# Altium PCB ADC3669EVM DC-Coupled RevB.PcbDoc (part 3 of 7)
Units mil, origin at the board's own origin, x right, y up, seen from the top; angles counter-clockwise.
Board outline 5000 x 2716.54 mil, 12 copper layers (Top Layer, L2 GND, L3 SIG, L4 GND, L5 PWR, L6 GND, L7 GND, L8 PWR, L9 GND, L10 PWR, L11 GND, Bottom Layer), stack 61 mil thick; 546 components, 341 nets, 2088 pads, 1256 vias.
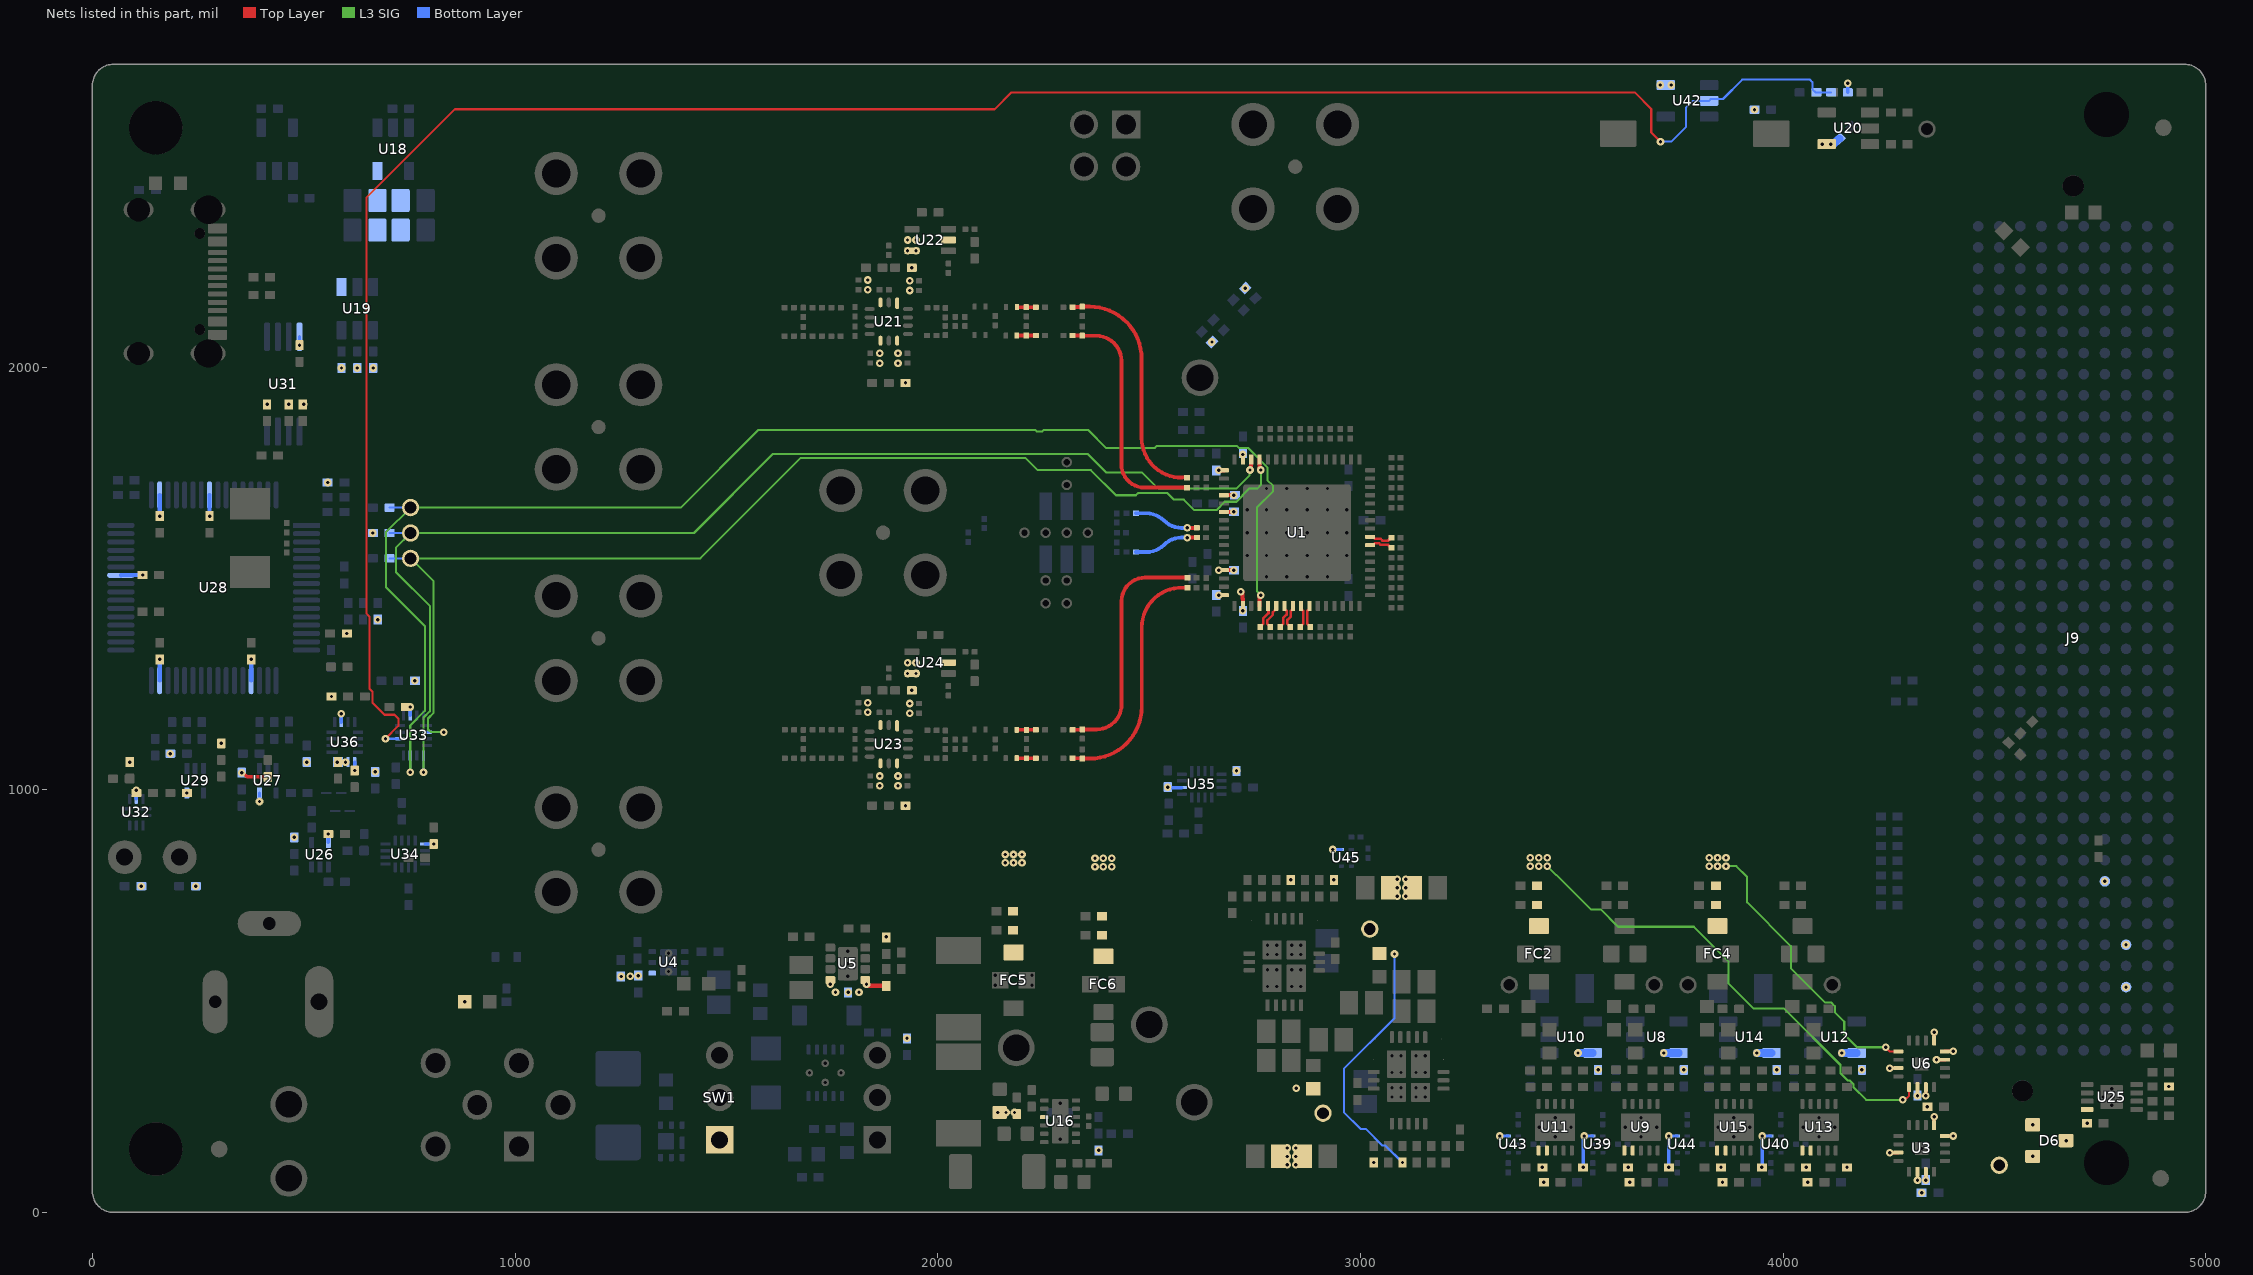
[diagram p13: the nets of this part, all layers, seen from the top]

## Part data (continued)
C96 C99 C115 C118: library part 0201RFCaps0738, "CAP THIN FILM 1PF 50V 0201", Alt Manufacturer=-, Manufacturer="KYOCERA AVX", Operating Temperature="-55°C ~ 125°C", Tolerance=±0.02pF, Voltage - Rated="50 V"
C126 C127 C130 C131 C140 C144 C145 C146 C149 C150 C159 C163: library part capcc05522, "CAP CER 10000PF 10V X7R 0201", Manufacturer="TDK Corporation", Operating Temperature="-55°C ~ 125°C", Ratings=AEC-Q200, Supplier Part Number 1=445-12059-1-ND, Temperature Coefficient=X7R, Tolerance=±10%, Voltage - Rated=10V
C128 C129 C132 C133 C147 C148 C151 C152: library part capcc04220, "CAP CER 2200PF 10V X7R 0201", Manufacturer="KYOCERA AVX", Operating Temperature="-55°C ~ 125°C", Ratings=-, Supplier Part Number 1=478-10777-1-ND, Temperature Coefficient=X7R, Tolerance=±10%, Voltage - Rated=10V
C135 C138 C154 C157: library part 0201RFCaps0065, "CAP CER 2PF 25V C0G/NP0 0201", Alt Manufacturer=-, Manufacturer="Murata Electronics", Operating Temperature="-55°C ~ 125°C", Temperature Coefficient="C0G, NP0", Tolerance=±0.05pF, Voltage - Rated=25V
C136 C155: library part 0201RFCaps0260, "CAP CER 0.7PF 25V C0G/NP0 0201", Alt Manufacturer=-, Manufacturer="Murata Electronics", Operating Temperature="-55°C ~ 125°C", Temperature Coefficient="C0G, NP0", Tolerance=±0.1pF, Voltage - Rated=25V
C137 C156: library part 0201RFCaps0405, "CAP CER 6.6PF 25V NP0 0201", Alt Manufacturer=-, Manufacturer="Murata Electronics", Operating Temperature="-55°C ~ 125°C", Temperature Coefficient="C0G, NP0", Tolerance=±0.25pF, Voltage - Rated=25V
C181 C182: library part capcc08351, "CAP CER 18PF 25V C0G/NP0 0201", Manufacturer="Murata Electronics", Operating Temperature="-55°C ~ 125°C", Ratings=-, Supplier Part Number 1=490-14486-1-ND, Temperature Coefficient="C0G, NP0", Tolerance=±2%, Voltage - Rated=25V
D1 D2 D7: library part cmp00247, "LED GREEN CLEAR CHIP SMD", Alt Manufacturer=-, Color=Green, Current Rating (Amps)=20mA, Manufacturer="Lite-On Inc.", Supplier Part Number 1=160-1888-1-ND, Voltage - Forward (Vf) (Typ)=3.2V
D3: library part cmp00440, "24.4V Clamp 24.6A Ipp Tvs Diode", Alt Manufacturer=-, Manufacturer=Littlefuse, Supplier Part Number 1=SMBJ15CALFCT-ND
D4: library part cmp00438, "DIODE SCHOTTKY 30V 1A SOD123", Alt Manufacturer="Rohm Semiconductor", Alt PartNumber=RB160M-30TR, Color=-, Manufacturer=Onsemi, Supplier Part Number 1=MBR130T1GOSCT-ND
D5: "Diode 40 V 3A Surface Mount PMDTM", Manufacturer="Rohm Semiconductor", Supplier Part Number 1=RBR3LAM40ACT-ND
D6: "Diode Array 1 Pair Common Cathode 20 V 400mA (DC)", Alt Manufacturer=-, Manufacturer="Diodes Inc", Supplier Part Number 1=SDM40E20LC-7DICT-ND
F1: library part cmp00082, "FUSE BOARD MOUNT 2.5A 32VDC 1206", Alt Manufacturer=-, Current Rating (Amps)="2.5 A", Manufacturer="Bourns Inc.", Supplier Part Number 1=SF-1206FP250-2CT-ND, Voltage Rating - DC="32 V"
F2: library part cmp00325, "EMI Filter Circuits 40 DB 50V 10A", Alt Manufacturer=-, Manufacturer="Murata Electronics", Supplier Part Number 1=81-BNX002-11
FB1 FB2 FB3 FB4 FB5 FB6 FB8: library part dcp00004, "8.5 Ohms @ 100 MHz 1 Power Line Ferrite Bead 0603 (1608 Metric) 8A 4mOhm", Current=8A, Manufacturer=Murata, Operating Temperature="-55°C ~ 125°C", Supplier Part Number 1=490-BLE18PS080SN1DCT-ND, Temperature Coefficient=-
FB11 FB12: library part dcp00209, "0402 (1005) 150OHM (TYP.) 1000MA", Current=1A, Manufacturer="Murata Electronics", Operating Temperature="-40°C ~ 85°C", Supplier Part Number 1=490-18375-1-ND, Temperature Coefficient=-
FC1 FC2 FC3 FC4 FC5 FC6: library part dcp00001, "Feed through capactior 27uF", Current=6A, Manufacturer=Murata, Operating Temperature="-40°C ~ 85°C", Supplier Part Number 1=490-6984-1-ND, Temperature Coefficient=-, Tolerance=±20%, Voltage - Rated=6.3V
FID1 FID2 FID3: library part mech00005, "Fiducial", Manufacturer=-
H5 H6: library part cmp00097, "Hex Standoff Threaded #4-40 Stainless Steel 1.250\" (31.75mm) 1 1/4", Alt Manufacturer=-, Manufacturer="RAF Electronic Hardware", Supplier Part Number 1=1772-1827-ND
J1: "Power Jack, mini, 2.1mm OD, R/A, TH", Alt Manufacturer=-, Manufacturer=Switchcraft, Supplier Part Number 1=SC1313-ND
J2 J4 J5 J6 J7 J8: "SMA Connector Jack, Female Socket 50Ohm Surface Mount, Through Hole Solder", Alt Manufacturer=-, Manufacturer="Amphenol RF", Supplier Part Number 1=ACX1962-ND
J3: "Header, 100mil, 2x2, Gold, TH", Alt Manufacturer="Sullins Connector Solutions", Alt PartNumber=PBC02DAAN, Color=-, Manufacturer=Samtec, Supplier Part Number 1=S2011E-02-ND
J9: "FMC, High Density Array, Male / EVM Connector 40x10", Alt Manufacturer=-, Manufacturer=Samtec, Supplier Part Number 1=SAM8730-ND
J10: "USB - C (Type - C) USB 2.0 Receptacle Connector 24 Position Surface Mount, Right Angle; Through Hole", Manufacturer=GCT, Supplier Part Number 1=2073-USB4105-GF-ACT-ND
L1 L2 L3 L4: library part indrf00113, "FIXED IND 2NH 600MA 120MOHM SMD", Alternate Manufacturer=-, Current Rating="600 mA", DC Resistance (DCR)="120mOhm Max", Frequency - Self Resonant=9GHz, Manufacturer="Murata Electronics", Operating Temperature="-55°C ~ 125°C", Package=0201, Q @ Freq="20 @ 500MHz", Supplier Part Number 1=490-13895-1-ND, Tolerance=±0.1nH
L5 L7 L9 L11: library part indrf00014, "RF Ceramic Chip Inductors", Alternate Manufacturer=-, Current Rating="260 mA", DC Resistance (DCR)="370 mΩ", Frequency - Self Resonant="6.25 GHz", Manufacturer=Coilcraft, Operating Temperature="-40°C ~ 125°C", Package=0201, Tolerance=±5%
L6 L8 L10 L12: library part indrf00011, "RF Ceramic Chip Inductors", Alternate Manufacturer=-, Current Rating="440 mA", DC Resistance (DCR)="155 mΩ", Frequency - Self Resonant="8 GHz", Manufacturer=Coilcraft, Operating Temperature="-40°C ~ 125°C", Package=0201, Tolerance=±5%
LBL1: library part cmp00106, "Thermal Transfer Printable Labels, 0.650\" W x 0.200\" H - 10,000 per roll", Alt Manufacturer=-, Manufacturer=Brady, Supplier Part Number 1=2267-THT-14-423-10-ND
Logo1: library part cmp00105, "FDL", Alt Manufacturer=-
Logo2: library part cmp00102, "FCC_disclaimer", Alt Manufacturer=-
Logo3: library part cmp00317, Alt Manufacturer=-, PartNumber="ESD Logo"
Logo4: library part cmp00101, Alt Manufacturer=-, PartNumber=WEEE_Minimum
LOGO5: library part cmp00103, "CE_Mark", Alt Manufacturer=-
Logo6: library part cmp00104, "Texas Instrument Corporate Signature", Alt Manufacturer=-, PartNumber="TI Bug"
NT1 NT2: library part cmp00320, "Single Point net tie", Alt Manufacturer=-, PartNumber=NetTie
PP1: "Probe Point that can be used in lue of a test point", Alt Manufacturer=-
PP2 PP3 PP4 PP5 PP6 PP8 PP11 PP12 PP13 PP14: library part cmp00025, "Probe Point that can be used in lue of a test point", Alt Manufacturer=-
Q1: library part cmp00439, "Bipolar (BJT) Transistor NPN 40 V 200 mA 300MHz 300 mW", Alt Manufacturer=-, Manufacturer=Onsemi, PartNumber=SMMBT3904LT1G, Supplier Part Number 1=SMMBT3904LT1GOSCT-ND
Q2: library part cmp00159, "MOSFET, N-CH, 20 V, 10 A", Alt Manufacturer=-, Manufacturer="Texas Instruments", Supplier Part Number 1=296-39992-1-ND
R1 R188 R259 R266: library part RSMD040200005, "RES SMD 1K OHM 0.5% 1/16W 0402", Manufacturer="Panasonic Electronic Components", Operating Temperature="-55°C ~ 155°C", Power (Watts)="0.063W, 1/16W", Ratings=AEC-Q200, Resistance="1 kΩ", Supplier Part Number 1=P1.0KDECT-ND, Temperature Coefficient=±25ppm/°C, Tolerance=±0.5%
R2: library part RSMD040200026, "RES SMD 1M OHM 1% 1/10W 0402", Manufacturer="Panasonic Electronic Components", Operating Temperature="-55°C ~ 155°C", Power (Watts)="0.1W, 1/10W", Ratings=AEC-Q200, Resistance="1 MΩ", Supplier Part Number 1=P1.00MLCT-ND, Temperature Coefficient=±100ppm/°C, Tolerance=±1%
R3 R185 R186 R187 R207 R210 R245 R246 R249 R250 R251 R252 R253 R254 R257 R260 R261: library part RSMD040202592, "RES 4.7K OHM 1% 1/10W 0402", Manufacturer="Panasonic Electronic Components", Operating Temperature="-55°C ~ 175°C", Power (Watts)="0.1W, 1/10W", Ratings=AEC-Q200, Resistance="4.7 kΩ", Supplier Part Number 1=10-ERJ-H2RF4701XCT-ND, Temperature Coefficient=±100ppm/°C, Tolerance=±1%
R4: library part RSMD040201732, "RES SMD 26.7KOHM 0.1% 1/16W 0402", Manufacturer="Panasonic Electronic Components", Operating Temperature="-55°C ~ 155°C", Power (Watts)="0.063W, 1/16W", Ratings=AEC-Q200, Resistance="26.7 kΩ", Supplier Part Number 1=P17789CT-ND, Temperature Coefficient=±15ppm/°C, Tolerance=±0.1%
R5: library part RSMD040200944, "RES SMD 162K OHM 1% 1/10W 0402", Manufacturer="Panasonic Electronic Components", Operating Temperature="-55°C ~ 155°C", Power (Watts)="0.1W, 1/10W", Ratings=AEC-Q200, Resistance="162 kΩ", Supplier Part Number 1=P162KLCT-ND, Temperature Coefficient=±100ppm/°C, Tolerance=±1%
R6 R7 R8 R13 R14 R19 R22 R28 R31 R36 R39 R45 R48 R61 R62 R64 R65 R73 R78 R125 R153 R172 R196 R209 R216 R241 R242 R243: library part RSMD040200314, "RES SMD 10K OHM 1% 1/10W 0402", Manufacturer="Panasonic Electronic Components", Operating Temperature="-55°C ~ 155°C", Power (Watts)="0.1W, 1/10W", Ratings=AEC-Q200, Resistance="10 kΩ", Supplier Part Number 1=P10.0KLCT-ND, Temperature Coefficient=±100ppm/°C, Tolerance=±1%
R9: library part RSMD040202967, "RES SMD 5.6K OHM 0.1% 1/16W 0402", Manufacturer="Panasonic Electronic Components", Operating Temperature="-55°C ~ 155°C", Power (Watts)="0.063W, 1/16W", Ratings=AEC-Q200, Resistance="5.6 kΩ", Supplier Part Number 1=P5.6KCNCT-ND, Temperature Coefficient=±15ppm/°C, Tolerance=±0.1%
R10: library part RSMD040202418, "RES SMD 37.4KOHM 0.1% 1/16W 0402", Manufacturer="Panasonic Electronic Components", Operating Temperature="-55°C ~ 155°C", Power (Watts)="0.063W, 1/16W", Ratings=AEC-Q200, Resistance="37.4 kΩ", Supplier Part Number 1=P37.4KDCCT-ND, Temperature Coefficient=±25ppm/°C, Tolerance=±0.1%
R11 R12 R44 R52 R240: library part RSMD040200520, "RES SMD 12K OHM 0.1% 1/16W 0402", Manufacturer="Panasonic Electronic Components", Operating Temperature="-55°C ~ 155°C", Power (Watts)="0.063W, 1/16W", Ratings=AEC-Q200, Resistance="12 kΩ", Supplier Part Number 1=P12KCPCT-ND, Temperature Coefficient=±10ppm/°C, Tolerance=±0.1%
R15 R67: library part RSMD040203749, "RES SMD 80.6KOHM 0.1% 1/16W 0402", Manufacturer="Panasonic Electronic Components", Operating Temperature="-55°C ~ 155°C", Power (Watts)="0.063W, 1/16W", Ratings=AEC-Q200, Resistance="80.6 kΩ", Supplier Part Number 1=P80.6KDCCT-ND, Temperature Coefficient=±25ppm/°C, Tolerance=±0.1%
R16: library part RSMD040203923, "RES SMD 9.31KOHM 0.1% 1/16W 0402", Manufacturer="Panasonic Electronic Components", Operating Temperature="-55°C ~ 155°C", Power (Watts)="0.063W, 1/16W", Ratings=AEC-Q200, Resistance="9.31 kΩ", Supplier Part Number 1=P9.31KDCCT-ND, Temperature Coefficient=±25ppm/°C, Tolerance=±0.1%
R17 R26 R34 R43 R51 R69 R74 R75 R79 R80 R111 R121 R124 R126 R127 R128 R139 R178 R179 R180 R181 R189 R190 R191 R193 R194 R195 R197 R198 R199 R200 R201 R204 R212 R213 R214 R215 R218 R219 R220 R222 R248 R256 R262 R263 R267: library part RSMD040200001, "RES SMD 0 OHM JUMPER 1/10W 0402", Manufacturer="Panasonic Electronic Components", Operating Temperature="-55°C ~ 155°C", Power (Watts)="0.1W, 1/10W", Ratings=AEC-Q200, Resistance="0 Ω", Supplier Part Number 1=P0.0JCT-ND, Temperature Coefficient=-, Tolerance=Jumper
R18: library part RSMD040202615, "RES SMD 4.87KOHM 0.1% 1/16W 0402", Manufacturer="Panasonic Electronic Components", Operating Temperature="-55°C ~ 155°C", Power (Watts)="0.063W, 1/16W", Ratings=AEC-Q200, Resistance="4.87 kΩ", Supplier Part Number 1=P4.87KDCCT-ND, Temperature Coefficient=±25ppm/°C, Tolerance=±0.1%
R20 R29 R37 R46: library part RSMD060312209, "RES 0.02 OHM 1% 1/3W 0603", Manufacturer="Panasonic Electronic Components", Operating Temperature="-55°C ~ 155°C", Power (Watts)="0.333W, 1/3W", Ratings=AEC-Q200, Resistance="20 mΩ", Supplier Part Number 1=P17461CT-ND, Temperature Coefficient=±250ppm/°C, Tolerance=±1%
R21 R30: library part RSMD040203023, "RES SMD 51.1K OHM 1% 1/10W 0402", Manufacturer="Panasonic Electronic Components", Operating Temperature="-55°C ~ 155°C", Power (Watts)="0.1W, 1/10W", Ratings=AEC-Q200, Resistance="51.1 kΩ", Supplier Part Number 1=P51.1KLCT-ND, Temperature Coefficient=±100ppm/°C, Tolerance=±1%
R23 R32 R40 R49 R60 R63 R71 R72 R76 R77 R81 R82 R83 R84 R85 R86 R87 R88 R89 R90 R91 R92 R93 R94 R95 R96 R97 R98 R99 R100 R101 R102 R103 R104 R105 R106 R107 R108 R109 R110 R114 R115 R116 R117 R118 R119 R120 R140 R146 R147 R159 R165 R166 R272: library part RSMD020101699, "RES SMD 0 OHM JUMPER 1/20W 0201", Manufacturer="Panasonic Electronic Components", Operating Temperature="-55°C ~ 125°C", Power (Watts)="0.05W, 1/20W", Resistance="0 Ω", Supplier Part Number 1=P15979CT-ND, Tolerance=Jumper
R24 R33 R41 R50: library part RSMD040200547, "RES SMD 12.4K OHM 1% 1/10W 0402", Manufacturer="Panasonic Electronic Components", Operating Temperature="-55°C ~ 155°C", Power (Watts)="0.1W, 1/10W", Ratings=AEC-Q200, Resistance="12.4 kΩ", Supplier Part Number 1=P12.4KLCT-ND, Temperature Coefficient=±100ppm/°C, Tolerance=±1%
R25 R42: library part RSMD120607125, "RES SMD 0 OHM JUMPER 1/4W 1206", Manufacturer="Panasonic Electronic Components", Operating Temperature="-55°C ~ 155°C", Power (Watts)="0.25W, 1/4W", Ratings=AEC-Q200, Resistance="0 Ω", Supplier Part Number 1=ERJ-S080R00V-ND, Temperature Coefficient=-, Tolerance=Jumper
R27 R35: library part RSMD040203700, "RES SMD 8.06KOHM 0.1% 1/16W 0402", Manufacturer="Panasonic Electronic Components", Operating Temperature="-55°C ~ 155°C", Power (Watts)="0.063W, 1/16W", Ratings=AEC-Q200, Resistance="8.06 kΩ", Supplier Part Number 1=P17902CT-ND, Temperature Coefficient=±15ppm/°C, Tolerance=±0.1%
R38 R47: library part RSMD040203879, "RES SMD 88.7K OHM 1% 1/10W 0402", Manufacturer="Panasonic Electronic Components", Operating Temperature="-55°C ~ 155°C", Power (Watts)="0.1W, 1/10W", Ratings=AEC-Q200, Resistance="88.7 kΩ", Supplier Part Number 1=P88.7KLCT-ND, Temperature Coefficient=±100ppm/°C, Tolerance=±1%
R53: library part RSMD040201564, "RES SMD 23.2KOHM 0.1% 1/16W 0402", Manufacturer="Panasonic Electronic Components", Operating Temperature="-55°C ~ 155°C", Power (Watts)="0.063W, 1/16W", Ratings=AEC-Q200, Resistance="23.2 kΩ", Supplier Part Number 1=P23.2KDCCT-ND, Temperature Coefficient=±25ppm/°C, Tolerance=±0.1%
R54 R58: library part CMP-0016044-3, "RES, 0, 5%, 0.75 W, AEC-Q200 Grade 0, 2010", Manufacturer=Vishay-Dale, Power_W=750mW, Supplier Part Number 1=541-0.0WCT-ND, TempCo=ppm/C, Tolerance_%=5%, Value2=0.75W, Value_Code=0000, ValueDisplayed=0
R55: library part RSMD040202194, "RES SMD 324 OHM 0.1% 1/16W 0402", Manufacturer="Panasonic Electronic Components", Operating Temperature="-55°C ~ 155°C", Power (Watts)="0.063W, 1/16W", Ratings=AEC-Q200, Resistance="324 Ω", Supplier Part Number 1=P324DCCT-ND, Temperature Coefficient=±25ppm/°C, Tolerance=±0.1%
R56 R57: library part RSMD040200357, "RES SMD 100K OHM 0.1% 1/16W 0402", Manufacturer="Panasonic Electronic Components", Operating Temperature="-55°C ~ 155°C", Power (Watts)="0.063W, 1/16W", Ratings=AEC-Q200, Resistance="100 kΩ", Supplier Part Number 1=P100KDCCT-ND, Temperature Coefficient=±25ppm/°C, Tolerance=±0.1%
R59: library part RSMD080510615, "RES SMD 0 OHM JUMPER 1/8W 0805", Manufacturer="Panasonic Electronic Components", Operating Temperature="-55°C ~ 155°C", Power (Watts)="0.125W, 1/8W", Ratings=AEC-Q200, Resistance="0 Ω", Supplier Part Number 1=P0.0ACT-ND, Temperature Coefficient=-, Tolerance=Jumper
R66: library part RSMD040200004, "RES 0 OHM JUMPER 0402 SMD", Manufacturer="Panasonic Electronic Components", Operating Temperature="-55°C ~ 155°C", Power (Watts)="0.1W, 1/10W", Ratings=AEC-Q200, Resistance="0 Ω", Supplier Part Number 1=10-ERJ-U020R00XCT-ND, Temperature Coefficient="-100/ +600ppm/°C", Tolerance=Jumper
R68: library part RSMD040203577, "RES SMD 7.87KOHM 0.1% 1/16W 0402", Manufacturer="Panasonic Electronic Components", Operating Temperature="-55°C ~ 155°C", Power (Watts)="0.063W, 1/16W", Ratings=AEC-Q200, Resistance="7.87 kΩ", Supplier Part Number 1=P7.87KDCCT-ND, Temperature Coefficient=±25ppm/°C, Tolerance=±0.1%
R70: library part RSMD040200273, "RES SMD 1.8K OHM 0.1% 1/16W 0402", Manufacturer="Panasonic Electronic Components", Operating Temperature="-55°C ~ 155°C", Power (Watts)="0.063W, 1/16W", Ratings=AEC-Q200, Resistance="1.8 kΩ", Supplier Part Number 1=10-ERA-2ARB182XCT-ND, Temperature Coefficient=±10ppm/°C, Tolerance=±0.1%
R112 R113 R122 R123 R157 R176: library part RSMD040200311, "RES SMD 10K OHM 1% 1/5W 0402", Manufacturer="Panasonic Electronic Components", Operating Temperature="-55°C ~ 155°C", Power (Watts)="0.2W, 1/5W", Ratings=AEC-Q200, Resistance="10 kΩ", Supplier Part Number 1=P17230CT-ND, Temperature Coefficient=±100ppm/°C, Tolerance=±1%
R129 R130 R134 R137 R138: library part RSMD020100423, "RES 49.9 OHM 1% 1/20W 0201 SMD", Manufacturer="Panasonic Electronic Components", Operating Temperature="-55°C ~ 125°C", Power (Watts)="0.05W, 1/20W", Resistance="49.9 Ω", Supplier Part Number 1=10-ERJ-U01F49R9CTR-ND, Temperature Coefficient=±200ppm/°C, Tolerance=±1%
R131 R136: library part RSMD020100201, "RES SMD 499 OHM 1% 1/20W 0201", Manufacturer="Panasonic Electronic Components", Operating Temperature="-55°C ~ 125°C", Power (Watts)="0.05W, 1/20W", Resistance="499 Ω", Supplier Part Number 1=P123045CT-ND, Temperature Coefficient=±200ppm/°C, Tolerance=±1%
R132 R135: library part RSMD020100013, "RES SMD 33 OHM 1% 1/20W 0201", Manufacturer="Panasonic Electronic Components", Operating Temperature="-55°C ~ 125°C", Power (Watts)="0.05W, 1/20W", Resistance="33 Ω", Supplier Part Number 1=P122944CT-ND, Temperature Coefficient=±200ppm/°C, Tolerance=±1%
R133: library part RSMD020100289, "RES SMD 100 OHM 1% 1/20W 0201", Manufacturer="Panasonic Electronic Components", Operating Temperature="-55°C ~ 125°C", Power (Watts)="0.05W, 1/20W", Resistance="100 Ω", Supplier Part Number 1=P122654CT-ND, Temperature Coefficient=±200ppm/°C, Tolerance=±1%
R141 R158 R160 R177: library part RSMD020100324, "RES 22.6 OHM 1% 1/20W 0201 SMD", Manufacturer="Panasonic Electronic Components", Operating Temperature="-55°C ~ 125°C", Power (Watts)="0.05W, 1/20W", Resistance="22.6 Ω", Supplier Part Number 1=10-ERJ-U01F22R6CTR-ND, Temperature Coefficient=±200ppm/°C, Tolerance=±1%
R142 R149 R161 R168: library part RSMD020100228, "RES SMD 127 OHM 1% 1/20W 0201", Manufacturer="Panasonic Electronic Components", Operating Temperature="-55°C ~ 125°C", Power (Watts)="0.05W, 1/20W", Resistance="127 Ω", Supplier Part Number 1=P122704CT-ND, Temperature Coefficient=±200ppm/°C, Tolerance=±1%
R143 R150 R162 R169: library part RSMD020100033, "RES SMD 40.2 OHM 1% 1/20W 0201", Manufacturer="Panasonic Electronic Components", Operating Temperature="-55°C ~ 125°C", Power (Watts)="0.05W, 1/20W", Resistance="40.2 Ω", Supplier Part Number 1=P122995CT-ND, Temperature Coefficient=±200ppm/°C, Tolerance=±1%
R144 R163: library part RSMD020100044, "RES SMD 357 OHM 1% 1/20W 0201", Manufacturer="Panasonic Electronic Components", Operating Temperature="-55°C ~ 125°C", Power (Watts)="0.05W, 1/20W", Resistance="357 Ω", Supplier Part Number 1=P122956CT-ND, Temperature Coefficient=±200ppm/°C, Tolerance=±1%
R145 R156 R164 R175: library part RSMD020100735, "RES 10K OHM 1% 1/20W 0201 SMD", Manufacturer="Panasonic Electronic Components", Operating Temperature="-55°C ~ 125°C", Power (Watts)="0.05W, 1/20W", Resistance="10 kΩ", Supplier Part Number 1=10-ERJ-U01F1002CCT-ND, Temperature Coefficient=±200ppm/°C, Tolerance=±1%
R148 R167: library part RSMD020100281, "RES SMD 66.5 OHM 1% 1/20W 0201", Manufacturer="Panasonic Electronic Components", Operating Temperature="-55°C ~ 125°C", Power (Watts)="0.05W, 1/20W", Resistance="66.5 Ω", Supplier Part Number 1=P123123CT-ND, Temperature Coefficient=±200ppm/°C, Tolerance=±1%
R151 R170: library part RSMD040200008, "RES SMD 1K OHM 5% 1/10W 0402", Manufacturer="Panasonic Electronic Components", Operating Temperature="-55°C ~ 155°C", Power (Watts)="0.1W, 1/10W", Ratings=AEC-Q200, Resistance="1 kΩ", Supplier Part Number 1=P1.0KJCT-ND, Temperature Coefficient=±200ppm/°C, Tolerance=±5%
R152 R171: library part RSMD040203233, "RES SMD 590 OHM 1% 1/10W 0402", Manufacturer="Panasonic Electronic Components", Operating Temperature="-55°C ~ 155°C", Power (Watts)="0.1W, 1/10W", Ratings=AEC-Q200, Resistance="590 Ω", Supplier Part Number 1=P590LCT-ND, Temperature Coefficient=±100ppm/°C, Tolerance=±1%
R154 R155 R173 R174: library part RSMD020100261, "RES 1.5K OHM 1% 1/20W 0201 SMD", Manufacturer="Panasonic Electronic Components", Operating Temperature="-55°C ~ 125°C", Power (Watts)="0.05W, 1/20W", Resistance="1.5 kΩ", Supplier Part Number 1=10-ERJ-U01F1501CCT-ND, Temperature Coefficient=±200ppm/°C, Tolerance=±1%
R182 R183: library part RSMD060312289, "RES SMD 0 OHM JUMPER 1/10W 0603", Manufacturer="Panasonic Electronic Components", Operating Temperature="-55°C ~ 155°C", Power (Watts)="0.1W, 1/10W", Ratings=AEC-Q200, Resistance="0 Ω", Supplier Part Number 1=P0.0GCT-ND, Temperature Coefficient=-, Tolerance=Jumper
R184 R247 R255 R258 R264: library part RSMD040202585, "RES SMD 4.7K OHM 5% 1/10W 0402", Manufacturer="Panasonic Electronic Components", Operating Temperature="-55°C ~ 155°C", Power (Watts)="0.1W, 1/10W", Ratings=AEC-Q200, Resistance="4.7 kΩ", Supplier Part Number 1=P4.7KJCT-ND, Temperature Coefficient=±200ppm/°C, Tolerance=±5%
R192: library part RSMD060309678, "RES 100 OHM 5% 1/8W 0603", Manufacturer="Panasonic Electronic Components", Operating Temperature="-55°C ~ 175°C", Package / Case=0603, Power (Watts)="0.125W, 1/8W", Ratings=AEC-Q200, Temperature Coefficient=±200ppm/°C, Tolerance=±5%
R208 R211 R221: library part RSMD040200378, "RES 100 OHM 1% 1/10W 0402", Manufacturer="Panasonic Electronic Components", Operating Temperature="-55°C ~ 175°C", Power (Watts)="0.1W, 1/10W", Ratings=AEC-Q200, Resistance="100 Ω", Supplier Part Number 1=10-ERJ-H2RF1000XCT-ND, Temperature Coefficient=±100ppm/°C, Tolerance=±1%
R217 R244: library part RSMD040201203, "RES SMD 2.2K OHM 1% 1/10W 0402", Manufacturer="Panasonic Electronic Components", Operating Temperature="-55°C ~ 155°C", Power (Watts)="0.1W, 1/10W", Ratings=AEC-Q200, Resistance="2.2 kΩ", Supplier Part Number 1=P2.20KLCT-ND, Temperature Coefficient=±100ppm/°C, Tolerance=±1%
R224 R227 R229: library part RSMD040200331, "RES SMD 10 OHM 1% 1/10W 0402", Manufacturer="Panasonic Electronic Components", Operating Temperature="-55°C ~ 155°C", Power (Watts)="0.1W, 1/10W", Ratings=AEC-Q200, Resistance="10 Ω", Supplier Part Number 1=P10.0LCT-ND, Temperature Coefficient=±100ppm/°C, Tolerance=±1%
R225: library part RSMD040200006, "RES SMD 1K OHM 1% 1/10W 0402", Manufacturer="Panasonic Electronic Components", Operating Temperature="-55°C ~ 155°C", Power (Watts)="0.1W, 1/10W", Ratings=AEC-Q200, Resistance="1 kΩ", Supplier Part Number 1=P1.00KLCT-ND, Temperature Coefficient=±100ppm/°C, Tolerance=±1%
R273 R274 R275: library part RSMD040201162, "RES SMD 2K OHM 0.1% 1/16W 0402", Manufacturer="Panasonic Electronic Components", Operating Temperature="-55°C ~ 155°C", Power (Watts)="0.063W, 1/16W", Ratings=AEC-Q200, Resistance="2 kΩ", Supplier Part Number 1=P2.0KDCCT-ND, Temperature Coefficient=±25ppm/°C, Tolerance=±0.1%
SW1: "Switch Slide SPDT 12V, 500mA", Alt Manufacturer=-, Manufacturer="Wurth Elektronik", PartNumber=450301014042, Supplier Part Number 1=710-450301014042
SW2: library part cmp00234, "SWITCH TACTILE SPST-NO 0.05A 24V", Alt Manufacturer=-, Manufacturer="TE Connectivity", Supplier Part Number 1=A101402CT-ND
SW3: library part cmp00353, "Switch Slide SPDT 12V, 500mA", Alt Manufacturer=-, Manufacturer="Wurth Elektronik", Supplier Part Number 1=710-450301014042
T2: "1:2 CORE & WIRE Transformer, 10 to 3000 MHz, 50Ω", Alt Manufacturer=-, Manufacturer=Mini-Circuits, Supplier Part Number 1=3157-TCM2-33WX+CT-ND
TP1: library part cmp00040, "Test Point, Multipurpose, Red, TH", Alt Manufacturer=-, Color=Red, Manufacturer=Keystone, Supplier Part Number 1=36-5010-ND
TP2: "Test Point, Multipurpose, Black, TH", Alt Manufacturer=-, Color=Black, Manufacturer=Keystone, PartNumber=5011, Supplier Part Number 1=36-5011-ND
TP3: library part cmp00047, "Test Point, Multipurpose, Brown, TH", Alt Manufacturer=-, Color=Brown, Manufacturer=Keystone, Supplier Part Number 1=36-5125-ND
TP4: "Test Point, Multipurpose, Orange, TH", Alt Manufacturer=-, Color=Orange, Manufacturer=Keystone, PartNumber=5013, Supplier Part Number 1=36-5013-ND
TP5 TP6: "Test Point, Miniature, Blue, TH", Alt Manufacturer=-, Color=Blue, Manufacturer=Keystone, PartNumber=5117, Supplier Part Number 1=36-5117-ND
TP8: library part cmp00045, "Test Point, Multipurpose, Blue, TH", Alt Manufacturer=-, Color=Blue, Manufacturer=Keystone, Supplier Part Number 1=36-5127-ND
TP9: library part cmp00042, "Test Point, Multipurpose, White, TH", Alt Manufacturer=-, Color=White, Manufacturer=Keystone, Supplier Part Number 1=36-5012-ND
U1: library part cmp00321, "16-Bit 500-MSPS Analog-to-Digital Converter", Alt Manufacturer=-, Manufacturer="Texas Instruments", PartNumber=ADC3669
U2: library part cmp00157, "12V, 5A, 30mΩ eFuse with Adjustable +/-15% Accurate Current Limit, DRC0010J (VSON-10)", Alt Manufacturer=-, Manufacturer="Texas Instruments"
U3 U6: "16-Bit, 4-Channel, 1-kSPS, Delta-Sigma ADC with I2C Interface, RTE0016D (WQFN-16)", Alternate Manufacturer="Texas Instruments", Alternate PartNumber=ADS1119IRTET, Operating Temperature Range="-40 to 125 C"
U4: library part cmp00251, "300-mA, 18-V, Ultra-Low IQ, Low-Dropout Linear Voltage Regulator With Power-Good", Alt Manufacturer=-, Manufacturer="Texas Instruments", PartNumber=TPS7A2501DRV
U5: "17V Input 2A Synchronous Step-Down Converter MicroSiP Module With Integrated Inductor, SIL0008D (uSIP-8)", Alternate Manufacturer="Texas Instruments", Alternate PartNumber=TPS82140SILT
U7 U17: "3-V to 17-V, 3-A Low-Noise and Low-Ripple Buck Power Module with Integrated Ferrite Bead Filter Compensation", Alt Manufacturer=-, Manufacturer="Texas Instruments", Max Supply Voltage=17V, Min Supply Voltage=3V, Nominal Supply Current=5mA, Operating Temperature Range="-55°C to +125°C", Output Voltage=0.8-5.5V, PartNumber=TPSM82913RDU, Switching Frequency=1/2.2MHz
U8 U10 U12 U14: "26V, 350kHz current sense amplifier", Alt Manufacturer="Texas Instruments", Alt PartNumber=INA180B1IDBVT
U9 U11 U13 U15: library part cmp00169, "1-A, ultra-low noise, ultra-high PSRR, RF voltage regulator", Alt Manufacturer=-, Manufacturer="Texas Instruments", Supplier Part Number 1=296-TPS7A9401DSCRCT-ND
U16: "Low-Noise Positive- and Negative-Output Charge Pump With Integrated LDO", Alt Manufacturer=-, Manufacturer="Texas Instruments"
U18: "150-mA, 30-V, ultra-low-IQ, low-dropout voltage regulator with reverse current protection and enable", Alt Manufacturer=-, Manufacturer="Texas Instruments", Supplier Part Number 1=296-35484-1-ND
U19: "3 Rail Simple Power Sequencer with Fixed Time Delay", Manufacturer="Texas Instruments"
U20: library part cmp00229, "Push-pull, supply voltage supervisor with manual reset", Alt Manufacturer="Texas Instruments", Alt PartNumber=TPS3125J18DBVT, Color=-
U21 U23: "8GHz Ultra Wideband Fully Differential Amplifier, RMS0014A (UQFN-14)", Alternate Manufacturer="Texas Instruments", Alternate PartNumber=LMH5401IRMST, Operating Temperature Range="-40 to 85 C", Rating=Catalog
U22 U24: Alt Manufacturer="Texas Instruments", Supplier Part Number 1=296-35916-1-ND
U25: library part cmp00154, "EEPROM 64K 8KX8 1.8V SER EE IND 1/4AWP RPO", Alt Manufacturer=-, Manufacturer=Microchip, Supplier Part Number 1=24LC64FT-I/MNYCT-ND
U26: "0.8V→3.6V Single Bus Buffer Gate With 3-State Outputs. Active high enable.", Alt Manufacturer=-, Manufacturer="Texas Instruments"
U27: "Single Bus Buffer Gate With 3-State Outputs. Active high enable.", Alt Manufacturer=-, Manufacturer="Texas Instruments"
U28: library part cmp00204, "USB Interface IC USB HS to Quad UART/ SPI/JTAG/I2C LQFP-6", Alt Manufacturer=FTDI, Alt PartNumber=FT4232HL-TRAY, Color=-, Supplier Part Number 1=768-1026-1-ND
U29: "Single Bus Buffer Gate With 3-State Outputs. Active low enable.", Alt Manufacturer=-, Manufacturer="Texas Instruments"
U31: library part cmp00156, "1K Microwire Compatible Serial EEPROM", Alt Manufacturer=-, Manufacturer="Microchip Technology", Supplier Part Number 1=93LC46B-I/ST-ND
U32: library part cmp00300, "ESD-Protected, Low Capacitance, 2-Channel, 2:1 Switch, With Powered-off Protection", Alt Manufacturer=-, Manufacturer="Texas Instruments", PartNumber=TMUX154ERSWR
U33: "Low-Voltage 4-Bit 1-of-2 FET Multiplexer/Demultiplexe", Color=-, Manufacturer="Texas Instruments", PartNumber=SN74CBTLV3257RSVR, Supplier Part Number 1=296-35586-1-ND
U34 U35 U36: library part cmp00171, "Translation - Voltage Levels 4-bit dual-supply bus transceiver with 3-state outputs and independent direction control inputs", Alt Manufacturer="Texas Instruments", Alt PartNumber=SN74AXC4T774RSV, Color=-, Supplier Part Number 1=296-24741-1-ND
U39 U40 U43 U44 U45: library part cmp00518, "Low-Power Single 2-Input Positive-AND Gate", Color=-, Manufacturer="Texas Instruments", PartNumber=SN74AUP1G08DRYR, Supplier Part Number 1=296-SN74AUP1G08DRYRCT-ND
U41: "380-nA voltage monitor for 12-V rails", Alt Manufacturer="Texas Instruments", Alt PartNumber=TPS3847108DBVT
U42: "Single 1.65-V to 5.5-V inverter", Alt Manufacturer=-, Manufacturer="Texas Instruments"
Y1: library part cmp00323, "Crystal, 12 MHz, 18 pF, SMD", Frequency Stability=+/-30ppm, Frequency_Fixed=12MHz, Manufacturer="Abracon Corporation", Supplier Part Number 1=535-10634-1-ND
ZZ1: library part CMP-0003616-3, "This Assembly Note is for PCB labels only"
ZZ2: library part CMP-0077236-1
ZZ3: library part CMP-0077237-1
ZZ4: library part CMP-0077238-1

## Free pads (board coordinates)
  round 0 hole 105.91 unplated mask+1.97: 21(4765.34,117.76) 21(4765.42,2597.78)

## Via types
v1: diameter 18, hole 8, Top Layer to Bottom Layer, tented both sides, 1256 vias

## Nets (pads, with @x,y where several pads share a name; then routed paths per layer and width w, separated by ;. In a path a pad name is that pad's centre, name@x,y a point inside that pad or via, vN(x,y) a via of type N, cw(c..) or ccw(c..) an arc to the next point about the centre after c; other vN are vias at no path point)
1p8V_Utility: C9.2 C90.2 C165.2 C173.2 C186.1 C187.1 C190.1 R9.2 R79.2 R112.1 R113.1 R125.2 R178.2 R188.1 R189.2 R249.2 R250.2 R257.2 U4.1 U20.5 U26.5 U27.5 U34.13 U35.14 U36.13 U42.5 | length 226.9
  Top Layer w8: v1(353.29,1040.48) 356,1040.48 365.84,1030.63 C173.2@415.07,1030.63
  Bottom Layer w8: v1(395.38,972.36) U27.5@395.38,992.36 ; U26.5@558.2,875.37 v1(558.2,895.37) ; v1(620.5,1045.51) U36.13@620.5,1065.51 ; U34.13@787.43,871.69 v1(807.43,871.69) ; v1(2544.26,1006.25) 2545.25,1005.26 U35.14@2577.41,1005.26 ; v1(4152.97,2672) 4153.04,2671.93 4153.04,2650.07 R250.2@4153.11,2650
  Bottom Layer w18: v1(4113.11,2527.6) 4119.83,2527.6 4132.24,2540 C90.2@4133.43,2540
  other v1: 1251.56,558.31 1272.56,558.98 1291.77,560.08 477.93,887.44 669.05,1042.41 2706.9,1044.63 304.91,1109.85 663.63,1607.55 2648.77,2059.39 2727.34,2186.89 4093.11,2527.6 3932.48,2609.21 3709.64,2667.4 3735.67,2667.4
2p3V_LDO: C19.2 C20.2 C23.2 C30.2 C37.2 C44.2 FB2.2 PP2.1 R16.2 R22.2 R31.2 R39.2 R48.2 U9.1 U9.2 U11.1 U11.2 U13.1 U13.2 U15.1 U15.2 | length 612
  Bottom Layer w5: v1(3080.72,611.39) 3080.72,459.59 2960.99,339.86 2960.99,236.79 3000.1,197.68 3012.94,197.68 3052.06,158.56 3059.14,158.56 v1(3099.64,118.06)
  other v1: 3434.07,71.52 3637,71.52 3856.75,71.52 4058.31,71.52 3430.56,106.52 3633.49,106.52 3853.24,106.52 4054.8,106.52 3086.97,748.48 3106.97,748.48 3086.97,768.48 3106.97,768.48 3086.97,788.48 3106.97,788.48
3p3V_AUX: D6.1 J9.D32
  other v1: 4590.63,207.4 4761.42,783.27
3p3V_EEPROM: C164.2 D6.3 R184.2 U25.8
  other v1: 4670,170 4719.22,211.18 4912.84,297.98
3p3V_Utility: C5.2 C6.2 C10.2 C11.2 C12.2 C22.2 C29.2 C36.2 C43.2 C168.2 C169.2 C170.2 C171.2 C172.2 C176.2 C180.2 C183.2 C184.2 C189.2 D2.1 D6.2 FB11.1 FB12.1 R6.2 R10.2 R13.2 R19.2 R28.2 R36.2 R45.2 R64.2 R209.2 R217.2 R224.2 R241.2 R242.2 R243.2 R245.2 R246.2 R247.2 R254.2 R255.2 R264.2 R273.2 R274.2 R275.2 U3.1 U3.7 U3.10 U3.11 U3.16 U5.4 U5.5 U6.1 U6.7 U6.10 U6.11 U6.15 U6.16 U8.5 U10.5 U12.5 U14.5 U28.20 U28.31 U28.42 U28.50 U28.56 U29.5 U31.8 U32.9 U33.14 U36.6 U36.14 U36.15 U36.16 U39.6 U40.6 U43.6 U44.6 U45.6 | length 1066.9
  Top Layer w8: v1(4252.68,141.6) U3.7@4272.68,141.6 ; v1(4252.69,341.6) U6.7@4272.68,341.6 ; v1(4317.96,76.33) U3.10@4317.96,96.33 ; v1(4317.96,276.32) U6.10@4317.96,296.33 ; v1(4337.64,76.33) U3.11@4337.64,96.33 ; v1(4337.65,276.32) U6.11@4337.64,296.33 ; U3.1@4357.33,206.56 v1(4357.33,226.56) ; U6.1@4357.33,406.56 v1(4357.33,426.56) ; v1(4362.92,361.28) U6.15@4382.92,361.29 ; U3.16@4382.92,180.97 v1(4402.92,180.97) ; U6.16@4382.92,380.97 v1(4402.92,380.97)
  Top Layer w10: v1(1831.47,540.26) ccw(c1835.57,540.26) 1835.57,536.15 R10.2@1878.52,536.15
  Bottom Layer w8: U32.9@104,978.5 v1(104,998.5) ; v1(490.07,2051.88) U31.8@490.07,2071.88 ; U36.6@589,1160 v1(589,1180) ; U33.14@752,1175.75 v1(752,1195.75) ; v1(2934.77,858.76) U45.6@2954.77,858.76 ; v1(3329.82,180.97) U43.6@3349.82,180.97 ; v1(3526.98,106.52) 3526.98,175.43 3529.82,178.27 v1(3529.82,180.97) U39.6@3549.82,180.97 ; v1(3729.91,106.52) 3729.82,106.52 v1(3729.82,180.97) U44.6@3749.82,180.97 ; v1(3949.67,106.52) 3951.13,106.52 v1(3951.13,180.97) U40.6@3971.13,180.97
  Bottom Layer w10: U28.42@67.63,1507.51 67.97,1507.85 118.38,1507.85 v1(118.77,1508.23) ; U28.31@159.16,1258.49 v1(159.16,1308.49) ; v1(159.16,1647.47) U28.50@159.16,1697.47 ; v1(277.27,1647.47) U28.56@277.27,1697.47 ; U28.20@375.7,1258.49 v1(375.7,1308.49)
  Bottom Layer w18: v1(3514.82,377.23) U10.5@3549.82,377.23 ; v1(3717.75,377.23) U8.5@3752.75,377.23 ; v1(3937.5,377.23) U14.5@3972.5,377.23 ; v1(4139.06,377.23) U12.5@4174.06,377.23
  other v1: 4327.8,46.52 4151.22,106.52 3031.64,118.06 4590.63,132.6 4341.22,250.04 3562.31,337.49 3765.24,337.49 3985,337.49 4186.55,337.49 1927.43,411.74 881.05,498.46 1787.87,520.71 1758.16,521.01 1813.85,520.97 1745.46,540.26 1878.52,652.48 115.82,772.13 244.7,772.13 2937,787.11 223.64,992.36 88.25,1065.51 507.33,1065.51 579.13,1065.51 598.88,1065.51 184.27,1085.63 565.82,1220.56 762.83,1257.76 601.9,1369.71 675.19,1402.59 556.57,1727.04 413.3,1911.84 464.48,1911.84 500.07,1911.84 589.45,1997.87 626.85,1997.87 664.25,1997.87
3p9V_LMH: C77.2 C78.2 C126.2 C127.2 C128.2 C129.2 C145.2 C146.2 C147.2 C148.2 FC6.3 R151.2 R153.2 R170.2 R172.2 U21.1 U21.10 U22.5 U23.1 U23.10 U24.5
  other v1: 2372,817.78 2392,817.78 2412,817.78 2372,837.78 2392,837.78 2412,837.78 1923.62,962.56 1906.1,1009.56 1906.1,1032.56 1933.93,1181.15 1933.93,1204.15 1938.62,1235.12 1928.62,1275.12 1948.62,1275.12 1923.62,1962.56 1906.1,2009.56 1906.1,2032.56 1933.93,2181.15 1933.93,2204.15 1938.62,2235.12 1928.62,2275.12 1948.62,2275.12
4p3V_LDO: C50.2 C51.2 C64.2 C65.2 FB8.2 PP8.1 R68.2 R73.2 U16.3
  other v1: 2827.05,112.44 2847.05,112.44 2827.05,132.44 2847.05,132.44 2380.54,147.14 2827.05,152.44 2847.05,152.44 2141.65,236.42 2161.65,236.42 2181.65,236.42 2848.35,294.22 2835,787.11
5V: C56.2 C57.2 C58.2 C67.2 U18.5 U19.1
12V_FMC: J9.C35 J9.C37 PP1.1 SW1.3
  other v1: 4811.42,533.27 4811.42,633.27
-1p1V_LMH: C71.2 C72.2 C130.2 C131.2 C132.2 C133.2 C149.2 C150.2 C151.2 C152.2 FC5.3 U21.3 U21.8 U22.2 U23.3 U23.8 U24.2
  other v1: 2159.39,826.98 2179.39,826.98 2199.39,826.98 2159.39,846.98 2179.39,846.98 2199.39,846.98 1862.4,1009.56 1862.4,1032.56 1834.56,1183.12 1834.56,1206.12 1928.62,1300.71 1948.62,1300.71 1862.4,2009.56 1862.4,2032.56 1834.56,2183.12 1834.56,2206.12 1928.62,2300.71 1948.62,2300.71
ADC_RESET: R250.1 R253.2 U33.10 U42.2 | length 5132.2
  Top Layer w5: v1(693.37,1120.63) 723.87,1151.13 723.87,1168.55 714.8,1177.63 691.06,1177.63 662.87,1205.81 662.87,1231.94 655.69,1239.12 655.69,1409.7 648.13,1417.26 648.13,2400.39 857.74,2610 2134.6,2610 2174.6,2650 3648.93,2650 3688.21,2610.72 3688.21,2555.15 v1(3709.9,2533.46)
  Bottom Layer w5: v1(693.37,1120.63) U33.10@728.37,1120.63 ; v1(3709.9,2533.46) 3735.66,2533.46 3770.04,2567.84 3770.04,2613.42 3786.62,2630 U42.2@3825,2630 3829.23,2634.23 3857.74,2634.23 3903.52,2680 4063.57,2680 4069.43,2674.14 4069.43,2657.34 4076.77,2650 R250.1@4113.74,2650
ADC_SCLK: PP12.1 R251.2 U1.13 U33.2 | length 2817.3
  Top Layer w9.5: U1.13@2761.42,1781.5 2761.42,1756.5 v1(2764.42,1756.5)
  L3 SIG w5: v1(831.37,1136.38) 800.29,1136.38 793.9,1142.77 793.9,1168.55 807.43,1182.08 807.43,1493.12 PP12.1@753,1547.55 1438.47,1547.55 1676.19,1785.27 2207.43,1785.27 2236.43,1756.27 2362.42,1756.27 2421.85,1696.84 2468.65,1696.84 2473.75,1701.93 2543.66,1701.93 2559.16,1686.43 2582.4,1686.43 2607.17,1661.67 2659.38,1661.67 2679.07,1681.35 2707,1681.35 2721.77,1696.12 2721.77,1697.59 2736.53,1712.35 2755.72,1712.35 2764.42,1721.05 v1(2764.42,1756.5)
  Bottom Layer w5: R251.2@703,1547.55 PP12.1@753,1547.55 ; U33.2@791.37,1136.38 v1(831.37,1136.38)
ADC_SDIO: PP14.1 R252.2 U1.36 U33.7 | length 3296.4
  Top Layer w9.5: U1.36@2761.42,1435.04 2761.42,1460.04 v1(2764.42,1460.04)
  L3 SIG w5: v1(752,1041.26) 752,1152.1 786.57,1186.67 786.57,1387.51 694.38,1479.7 694.38,1608.93 PP14.1@753,1667.55 1392.11,1667.55 1575.95,1851.39 2230.72,1851.39 2234.56,1847.54 2247.4,1847.54 2251.25,1851.39 2355.55,1851.39 2398.74,1808.21 2512.72,1808.21 2518.24,1813.73 2707.61,1813.73 2712.53,1808.81 2734.03,1808.81 2779.92,1762.92 2779.92,1732.62 2793.39,1719.15 2793.39,1706.36 2755.45,1668.43 2755.45,1469.47 2764.42,1460.51 v1(2764.42,1460.04)
  Bottom Layer w5: R252.2@703,1667.55 PP14.1@753,1667.55 ; v1(752,1041.26) U33.7@752,1081.26
ADC_SEN: PP13.1 R249.1 U1.14 U33.5 | length 2860.3
  Top Layer w9.5: v1(2738.73,1756.5) 2741.73,1756.5 U1.14@2741.73,1781.5
  L3 SIG w5: v1(783.49,1041.26) 783.49,1170.87 798.43,1185.81 798.43,1435.06 718.11,1515.38 718.11,1572.66 PP13.1@753,1607.55 1423.34,1607.55 1610.06,1794.27 2355.08,1794.27 2399.15,1750.21 2483.64,1750.21 2521.5,1712.35 2706.27,1712.35 2737.91,1743.99 2737.91,1755.67 v1(2738.73,1756.5)
  Bottom Layer w5: R249.1@703,1607.55 PP13.1@753,1607.55 ; v1(783.49,1041.26) U33.5@783.49,1081.26
AVDD12: C33.2 C34.2 C80.2 C81.2 C82.2 FC2.3 U1.15 U1.22 U1.34 U6.9 | length 1241
  Top Layer w5: v1(4283.27,266.33) 4286.79,266.33 4290.96,270.49 4292.44,270.49 4298.27,276.33 U6.9@4298.27,296.33
  Top Layer w9.5: U1.22@2676.77,1657.48 v1(2700.58,1657.48) ; v1(2717.05,1468.85) 2720.98,1468.85 2720.98,1452.69 2721.88,1451.8 2721.88,1435.21 U1.34@2722.05,1435.04 v1(2722.05,1423.23) ; U1.15@2722.05,1781.5 v1(2722.05,1793.31)
  L3 SIG w5: v1(3442.26,819.32) 3463.49,798.09 3464.11,798.09 3545.17,717.03 3568.39,717.03 3609.39,676.03 3788.55,676.03 3870.44,594.14 3870.44,542.12 3929.79,482.77 4001.94,482.77 4135.72,348.98 4135.72,329.31 4152.77,312.26 4157.64,312.26 4166.72,303.18 4166.72,296.03 4196.43,266.33 v1(4283.27,266.33)
  other v1: 3402.26,819.32 3422.26,819.32 3402.26,839.32 3422.26,839.32 3442.26,839.32
AVDD18: C47.2 C48.2 C85.2 C86.2 C87.2 C88.2 FC4.3 U1.17 U1.20 U1.29 U1.32 U6.5 | length 764.3
  Top Layer w5: v1(4242.68,390.97) 4252.68,380.97 U6.5@4272.68,380.97
  Top Layer w9.5: v1(2664.96,1460.63) U1.32@2676.77,1460.63 ; v1(2664.96,1519.69) U1.29@2676.77,1519.69 v1(2700.58,1519.69) ; v1(2664.96,1755.91) U1.17@2676.77,1755.91 ; U1.20@2676.77,1696.85 v1(2700.58,1696.85)
  L3 SIG w5: v1(3864.94,819.32) 3889.11,819.32 3914.88,793.55 3914.88,733.68 4018.5,630.06 4018.5,577.61 4098.98,497.13 4113.44,497.13 4122.52,488.05 4122.52,473.59 4144.8,451.31 4144.8,421.13 4174.96,390.97 v1(4242.68,390.97)
  other v1: 3824.94,819.32 3844.94,819.32 3824.94,839.32 3844.94,839.32 3864.94,839.32
CHA_AMP_OUT_N: C92.1 C135.2 L6.2 | length 44.8
  Top Layer w9: L6.2@2187.18,2141.82 C92.1@2232,2141.82
CHA_AMP_OUT_P: C101.2 C138.1 L8.2 | length 45
  Top Layer w9: L8.2@2187,2074.68 C101.2@2232,2074.72
CHA_IN_N: C99.1 L2.1 R130.2 | length 579.2
  Top Layer w9: R130.2@2318.59,2075.01 C99.1@2339.18,2075.01 ; C99.1@2341.59,2074.01 2375.39,2074.01 cw(c2375.39,2014.91) 2434.5,2014.91 2434.5,1770.23 ccw(c2489.88,1770.23) 2489.88,1714.86 L2.1@2590.23,1714.86
CHA_IN_P: C96.2 L1.1 R129.2 | length 578.7
  Top Layer w9: R129.2@2318.6,2142.1 C96.2@2339.18,2142.1 ; C96.2@2341.6,2143.1 2359.26,2143.1 cw(c2359.34,2020.09) 2482.35,2020.22 2482.35,1832.65 ccw(c2576.33,1832.58) L1.1@2588.33,1739.37
CHB_AMP_OUT_N: C111.2 C154.2 L10.2 | length 45.1
  Top Layer w9: L10.2@2187,1142 2187.18,1141.82 C111.2@2232,1141.82
CHB_AMP_OUT_P: C120.1 C157.1 L12.2 | length 45
  Top Layer w9: L12.2@2187,1074.68 C120.1@2232,1074.72 C120.1@2232,1074.72
CHB_IN_N: C118.1 L3.1 R138.2 | length 578.7
  Top Layer w9: R138.2@2319.1,1074.72 C118.1@2339.68,1074.72 ; C118.1@2342.1,1073.72 2359.76,1073.72 ccw(c2359.84,1196.74) 2482.85,1196.61 2482.85,1384.18 cw(c2576.83,1384.25) L3.1@2588.83,1477.46
CHB_IN_P: C115.2 L4.1 R137.2 | length 579.2
  Top Layer w9: R137.2@2319.09,1141.82 C115.2@2339.68,1141.82 ; C115.2@2342.09,1142.82 2375.89,1142.82 ccw(c2375.89,1201.92) 2435,1201.92 2435,1446.59 cw(c2490.38,1446.59) 2490.38,1501.97 L4.1@2590.73,1501.97
CLK_IN_N: C107.1 C108.2 R133.1 | length 153.3
  Top Layer w9: v1(2589.99,1596.71) C107.1@2612.99,1596.71
  Bottom Layer w9: C108.2@2468.88,1562.44 2493.88,1562.37 ccw(c2493.88,1620.98) 2535.32,1579.54 cw(c2576.77,1538.09) 2576.77,1596.71 v1(2589.99,1596.71)
CLK_IN_P: C105.2 C106.1 R133.2 | length 153.3
  Top Layer w9: v1(2589.99,1619.71) 2612.86,1619.71 C106.1@2612.99,1619.83
  Bottom Layer w9: C105.2@2468.88,1654.1 2493.88,1654.04 cw(c2493.88,1595.43) 2535.32,1636.88 ccw(c2576.77,1678.32) 2576.77,1619.71 v1(2589.99,1619.71)
DCLK_n: R83.1 U1.56 | length 56.5
  Top Layer w6: U1.56@3023.23,1598.43 3030.12,1598.43 3034.96,1593.58 3048.18,1593.58 3052.18,1589.58 3065.63,1589.58 R83.1@3069.14,1593.1 ; R83.1@3069.14,1593.13 3072.44,1596.43 R83.1@3073.23,1596.43
DCLK_p: R82.1 U1.55 | length 56.5
  Top Layer w6: U1.55@3023.23,1578.74 3030.12,1578.74 3034.96,1583.58 3044.04,1583.58 3048.04,1579.58 3065.63,1579.58 R82.1@3069.14,1576.07 ; R82.1@3069.14,1576.04 3072.44,1572.74 R82.1@3073.23,1572.74
DOUT0_n: R85.1 U1.37 | length 58.7
  Top Layer w6: R85.1@2763.1,1385.04 2763.1,1385.83 R85.1@2766.4,1389.13 ; R85.1@2766.43,1389.13 2769.95,1392.64 2769.95,1405.27 2782.56,1417.88 2782.56,1433.59 U1.37@2781.1,1435.04
DOUT0_p: R84.1 U1.38 | length 61.5
  Top Layer w6: R84.1@2783.46,1389.13 2779.95,1392.64 2779.95,1401.13 2792.56,1413.74 2792.56,1419.92 2800.79,1428.15 U1.38@2800.79,1435.04 ; R84.1@2783.49,1389.13 2786.79,1385.83 R84.1@2786.79,1385.04
DOUT1_n: R87.1 U1.39 | length 58.2
  Top Layer w6: R87.1@2810.5,1385.04 2810.47,1385.83 R87.1@2813.77,1389.13 ; R87.1@2813.8,1389.13 2817.32,1392.64 2817.32,1406.23 2825.32,1414.23 2825.32,1423.31 2820.47,1428.15 U1.39@2820.47,1435.04
DOUT1_p: R86.1 U1.40 | length 58.2
  Top Layer w6: R86.1@2834.16,1385.04 2834.16,1385.83 2830.86,1389.13 2827.32,1392.64 2827.32,1402.09 2835.32,1410.09 2835.32,1423.31 2840.16,1428.15 U1.40@2840.16,1435.04
DOUT2_n: R89.1 U1.41 | length 54.9
  Top Layer w6: R89.1@2857.84,1385.04 2857.84,1385.83 2861.14,1389.13 2864.69,1392.64 2864.69,1423.31 2859.84,1428.15 U1.41@2859.84,1435.04
DOUT2_p: R88.1 U1.42 | length 54.9
  Top Layer w6: R88.1@2878.2,1389.13 2874.69,1392.64 2874.69,1423.31 2879.53,1428.15 U1.42@2879.53,1435.04 ; R88.1@2878.23,1389.13 2881.53,1385.83 R88.1@2881.5,1385.04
